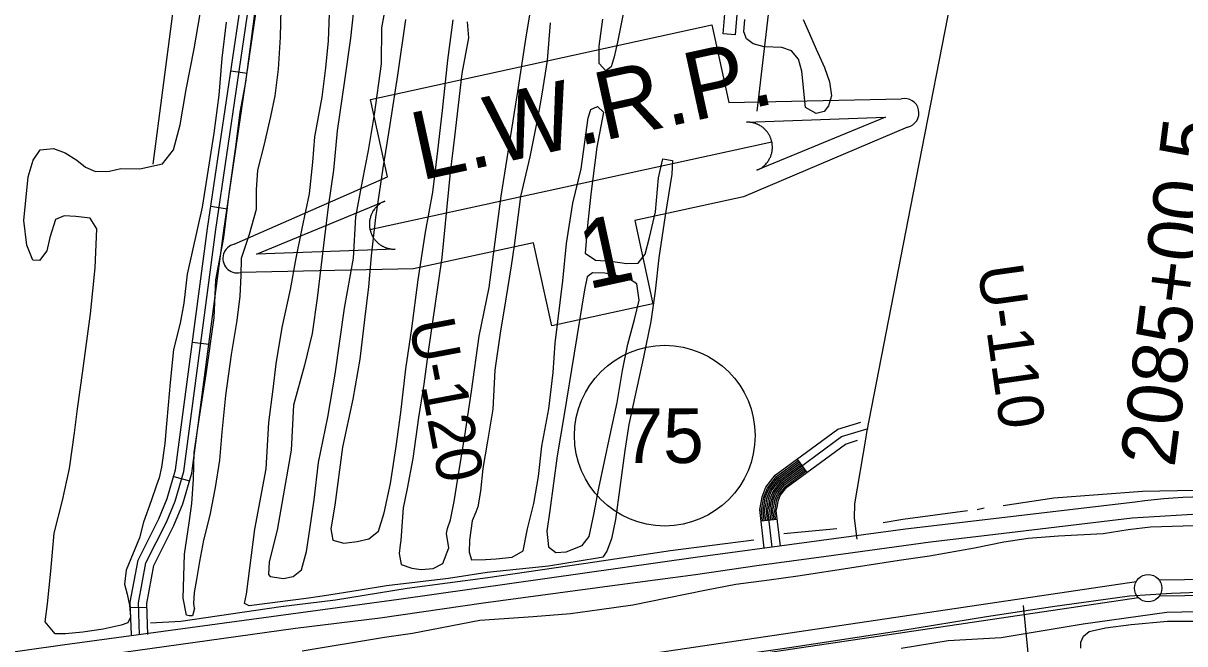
# Model space of a CAD drawing. Extents: x 3355677 to 3393573, y 612928 to 638357.
# Drawn here: x 3361105 to 3363227, y 625120 to 626253 of the extents above; entities that cross this region are included whole.
import ezdxf

# ---------------------------------------------------------------- set-up
doc = ezdxf.new("R2010")
doc.units = 0
for name, color, linetype in [('V-BLDG-OTLN', 7, 'Continuous'), ('V-FLOD-BASE', 7, 'Continuous'), ('V-LEVE-TOET', 7, 'Continuous'), ('V-RIVR-RANG', 7, 'Continuous'), ('V-RIVR-RANG-IDEN', 7, 'Continuous'), ('V-ROAD-CNTR', 7, 'Continuous'), ('V-ROAD-IDEN', 7, 'Continuous'), ('V-SITE-VEGE', 7, 'Continuous'), ('V-SURV-IDEN', 7, 'Continuous'), ('V-SURV-LINE', 7, 'Continuous'), ('V-TOPO-SHOR', 7, 'Continuous'), ('V-TOPO-WATR-IDEN', 7, 'Continuous')]:
    doc.layers.add(name, color=color, linetype=linetype)

msp = doc.modelspace()

# ---------------------------------------------------------------- linework, layer by layer
at = {"layer": 'V-BLDG-OTLN'}
msp.add_lwpolyline([(3362410, 626283.5), (3362406.1, 626232.2), (3362384.2, 626233.9), (3362388.1, 626285.1)], close=True, dxfattribs=at)
at = {"layer": 'V-FLOD-BASE'}
msp.add_lwpolyline([(3362000.8, 625039.3), (3362153.2, 625064.2), (3362360.8, 625092.7), (3362504.8, 625113.4), (3362708.5, 625144.1), (3362865.1, 625169.7), (3362985.4, 625188.2), (3363125.9, 625207.5), (3363202.8, 625212.6), (3363267.9, 625214.9), (3363381.2, 625216.6), (3363462.3, 625209.2), (3363630.2, 625192.8), (3363736.5, 625179.8), (3363859, 625167.6), (3363988.4, 625154.7), (3364110.1, 625139.6), (3364234, 625124.6), (3364270.4, 625117), (3364292.1, 625112.9)], dxfattribs=at)
at = {"layer": 'V-LEVE-TOET'}
for points in [[(3363323.1, 625337.9), (3363164.7, 625332.6), (3363123.5, 625328.3), (3363078.2, 625320.5), (3362996.6, 625316.7), (3362940.8, 625312.4), (3362896.8, 625305.3), (3362843.1, 625294.7), (3362760.8, 625279.8), (3362705.1, 625272), (3362587.9, 625253.5), (3362520.2, 625243.5), (3362467.9, 625236.4), (3362407.2, 625227.9), (3362353.5, 625217.9), (3362281.7, 625203.1), (3362218.9, 625190.4), (3362158.3, 625181.8), (3362105.3, 625174.7), (3362036.9, 625168.9), (3361939.2, 625162.4), (3361816.5, 625139), (3361765.6, 625131.2), (3361614.9, 625106.3)], [(3362709, 625111.7), (3362794.8, 625125.9), (3362891.7, 625131.7), (3363041.7, 625156.6), (3363194.4, 625177.9), (3363276.1, 625179.6), (3363339.6, 625178.3), (3363382.8, 625175.7), (3363437.3, 625174.4), (3363481.2, 625171.1), (3363538.5, 625165.6), (3363597.1, 625162.3), (3363659.2, 625154.1), (3363742.3, 625140.4), (3363811.4, 625130.1), (3363973.3, 625117.3)]]:
    msp.add_lwpolyline(points, dxfattribs=at)
at = {"layer": 'V-RIVR-RANG'}
msp.add_line((3362932, 625189.6), (3363059.6, 623895.8), dxfattribs=at)
at = {"layer": 'V-ROAD-CNTR'}
for p, q in [((3361484.7, 626166.2), (3361514.3, 626161.8)), ((3361448.2, 625918.9), (3361477.9, 625914.5)), ((3361414.7, 625670.9), (3361444.5, 625667)), ((3362519.1, 625457.1), (3362536.9, 625433)), ((3361380.3, 625425.7), (3361409.1, 625417.3)), ((3362453, 625344.3), (3362482.8, 625347.7)), ((3361301.4, 625186), (3361331.3, 625187))]:
    msp.add_line(p, q, dxfattribs=at)
for points in [[(3361333.1, 625137.1), (3361331.1, 625193.7), (3361343.9, 625263.1), (3361380.7, 625335.9), (3361396.9, 625375.4), (3361413.2, 625431.3), (3361472, 625874.4), (3361552.4, 626420.2), (3361626.5, 626944.1), (3361690.7, 627356), (3361764.8, 627926.7), (3361857.7, 628521.4), (3361932.7, 629031.3), (3361989.5, 629447.1), (3362043.4, 629781.8), (3362046.3, 629849.5), (3362026.4, 629885.3), (3362010.6, 629880.9)], [(3361303.1, 625136), (3361301, 625196), (3361315.2, 625272.8), (3361353.4, 625348.4), (3361368.5, 625385.3), (3361383.8, 625437.6), (3361442.3, 625878.6), (3361522.7, 626424.5), (3361596.8, 626948.5), (3361661, 627360.2), (3361735.1, 627930.9), (3361828, 628525.9), (3361903, 629035.5), (3361959.8, 629451.5), (3362013.5, 629784.8), (3362016, 629842.3), (3362011.6, 629850.1), (3362007.2, 629848.9), (3361989.5, 629843)], [(3361318.1, 625136.5), (3361316.1, 625194.9), (3361329.5, 625267.9), (3361367, 625342.1), (3361382.7, 625380.4), (3361398.5, 625434.5), (3361457.1, 625876.5), (3361537.6, 626422.4), (3361611.7, 626946.3), (3361675.9, 627358.1), (3361750, 627928.8), (3361842.9, 628523.6), (3361917.8, 629033.4), (3361974.6, 629449.3), (3362028.5, 629783.3), (3362031.1, 629845.9), (3362019, 629867.7), (3362002.8, 629863.2), (3361984.7, 629857.2)], [(3362866, 626637.9), (3362814.5, 626370.8), (3362726.3, 625918.7), (3362645.8, 625505.6), (3362643.6, 625493.9), (3362623.6, 625375.7), (3362623, 625349.1), (3362627.9, 625311)], [(3362458.7, 625294.6), (3362450.6, 625365), (3362453.5, 625377.9), (3362455.1, 625388.5), (3362462, 625405.8), (3362479.1, 625427.6), (3362593.4, 625511.8), (3362635.5, 625524.9)], [(3362473.6, 625296.3), (3362465.8, 625364.2), (3362468.3, 625375.2), (3362469.7, 625384.5), (3362475.1, 625398.2), (3362489.7, 625416.7), (3362600.2, 625498.3), (3362648.6, 625513.3)], [(3362488.5, 625298), (3362481, 625363.4), (3362483, 625372.4), (3362484.3, 625380.6), (3362488.3, 625390.7), (3362500.2, 625405.9), (3362607.1, 625484.7), (3362629.5, 625491.6)], [(3362456, 625344.6), (3362453.7, 625364.8), (3362456.5, 625377.4), (3362458, 625387.7), (3362464.6, 625404.3), (3362481.2, 625425.4), (3362520.9, 625454.7)], [(3362459, 625345), (3362456.7, 625364.7), (3362459.4, 625376.8), (3362460.9, 625386.9), (3362467.3, 625402.7), (3362483.3, 625423.2), (3362522.7, 625452.3)], [(3362461.9, 625345.3), (3362459.7, 625364.5), (3362462.4, 625376.3), (3362463.9, 625386.1), (3362469.9, 625401.2), (3362485.4, 625421.1), (3362524.5, 625449.9)], [(3362464.9, 625345.6), (3362462.8, 625364.4), (3362465.3, 625375.7), (3362466.8, 625385.3), (3362472.5, 625399.7), (3362487.5, 625418.9), (3362526.3, 625447.4)], [(3362467.9, 625346), (3362465.8, 625364.2), (3362468.3, 625375.2), (3362469.7, 625384.5), (3362475.1, 625398.2), (3362489.7, 625416.7), (3362528, 625445)], [(3362470.9, 625346.3), (3362468.9, 625364), (3362471.2, 625374.6), (3362472.6, 625383.7), (3362477.8, 625396.7), (3362491.8, 625414.6), (3362529.8, 625442.6)], [(3362473.9, 625346.7), (3362471.9, 625363.9), (3362474.2, 625374.1), (3362475.5, 625382.9), (3362480.4, 625395.2), (3362493.9, 625412.4), (3362531.6, 625440.2)], [(3362476.8, 625347), (3362474.9, 625363.7), (3362477.1, 625373.5), (3362478.4, 625382.2), (3362483, 625393.7), (3362496, 625410.2), (3362533.4, 625437.8)], [(3362479.8, 625347.3), (3362478, 625363.5), (3362480.1, 625373), (3362481.3, 625381.4), (3362485.6, 625392.2), (3362498.1, 625408), (3362535.2, 625435.4)], [(3363136.5, 625378.7), (3362716.8, 625329.1), (3362333.4, 625277.4), (3361791.5, 625201), (3361177, 625117.3), (3360797.8, 625064)]]:
    msp.add_lwpolyline(points, dxfattribs=at)
msp.add_arc((3363287.7, 624252.4), 1136.3, 83.5309, 97.6461, dxfattribs=at)
at = {"layer": 'V-ROAD-IDEN'}
msp.add_circle((3362277.3, 625500), 165, dxfattribs=at)
msp.add_circle((3362277.3, 625500), 165, dxfattribs=at)
at = {"layer": 'V-SITE-VEGE'}
for points in [[(3361916.3, 626255.8), (3361918.5, 626226.5), (3361906.8, 626161.5), (3361893.2, 626045.5), (3361885, 625980.5), (3361870.1, 625825.4), (3361857, 625737.4), (3361845.4, 625657.7), (3361837.2, 625594.1), (3361827.6, 625533.4), (3361817.3, 625458.6), (3361807, 625403.4), (3361799.4, 625368.4), (3361795.4, 625309), (3361794, 625300.7), (3361792, 625284.6), (3361795.5, 625265), (3361815.1, 625258.1), (3361832.5, 625255.4), (3361854.2, 625257.5), (3361871.6, 625266.7), (3361882.7, 625295.3), (3361878.5, 625321.2), (3361880.5, 625330.2), (3361886.1, 625346.3), (3361892.3, 625379.9), (3361899.1, 625421.8), (3361912.2, 625499.4), (3361924.5, 625580.4), (3361938.2, 625681.7), (3361956.8, 625770.5), (3361978.7, 625937.5), (3362008.9, 626128.3), (3362024.7, 626231.7), (3362042.5, 626337.2)], [(3361476.3, 626255.3), (3361468.1, 626189.6), (3361462.7, 626121.9), (3361453.8, 626052.7), (3361441.5, 625975.1), (3361432.5, 625917.1), (3361405, 625794.8), (3361398.8, 625741.7), (3361391.9, 625705.3), (3361380.2, 625657.1), (3361374.1, 625597), (3361370, 625555.8), (3361367.3, 625521.6), (3361363.9, 625485.9), (3361357.7, 625442.6), (3361353.6, 625423.1), (3361348.8, 625409.8), (3361339.1, 625381.1), (3361325.2, 625341.9), (3361317.6, 625313.3), (3361293.3, 625254.5), (3361290.6, 625228.7), (3361295.5, 625210.5), (3361299.8, 625190.3), (3361301.2, 625168.7), (3361296.4, 625158.2), (3361284.5, 625153.9), (3361251.7, 625146.9), (3361214, 625141.2), (3361182.6, 625138.3), (3361163.7, 625138.2), (3361145.5, 625159.8), (3361149.6, 625192.7), (3361155.7, 625252.8), (3361161.8, 625321.9), (3361177, 625381.3), (3361190.1, 625440.1), (3361199, 625505), (3361204.5, 625549.1), (3361214.1, 625618.2), (3361228.4, 625722.4), (3361236.6, 625806.2), (3361239.9, 625877.5), (3361227.9, 625897), (3361201.4, 625900.4), (3361180.4, 625901.7), (3361164.4, 625894.7), (3361154, 625861.8), (3361148.5, 625837.4), (3361135.3, 625819.9), (3361122.7, 625820.5), (3361112.1, 625847.8), (3361106.4, 625893.1), (3361114.6, 625972.8), (3361123.6, 626002.9), (3361136.1, 626021.7), (3361160.5, 626024.6), (3361182.2, 626016.3), (3361203.2, 626003.1), (3361219.3, 625990.5), (3361237.5, 625982.2), (3361263.3, 625983), (3361283.6, 625987.9), (3361318.5, 625987.3), (3361359.7, 625996.5), (3361379.9, 626021.7), (3361392.3, 626067.9), (3361403.3, 626132.2), (3361417.8, 626206.2), (3361432.2, 626291.5)], [(3361576.1, 626279.3), (3361574.9, 626227.6), (3361570.8, 626169), (3361564.7, 626120.7), (3361557.1, 626083), (3361544.7, 626029.9), (3361533.6, 625985.1), (3361530.9, 625948.8), (3361531, 625913.2), (3361517.9, 625867.1), (3361503.4, 625823.7), (3361502.7, 625792.3), (3361500.8, 625754.6), (3361495.3, 625710.5), (3361485, 625648.3), (3361474.7, 625573.6), (3361467.9, 625506.5), (3361463.9, 625455.5), (3361456.3, 625405.2), (3361446, 625354.9), (3361435, 625309.4), (3361427.4, 625270.3), (3361421.9, 625237.4), (3361417.8, 625213.7), (3361416.4, 625193.4), (3361417.8, 625185.1), (3361418.5, 625184.4), (3361414.4, 625171.1), (3361408.8, 625171.1), (3361403.9, 625172.4), (3361397.5, 625203.2), (3361400.1, 625283.5), (3361408.3, 625340.8), (3361413.1, 625376.4), (3361416.5, 625420.4), (3361417.7, 625469.3), (3361428, 625537.8), (3361439.7, 625612.6), (3361454.1, 625715.3), (3361457.4, 625784.5), (3361471.8, 625862), (3361481.4, 625941.7), (3361493.7, 626027.6), (3361501.9, 626090.5), (3361512.2, 626145.7), (3361530.7, 626289)], [(3361710.9, 626299.3), (3361703.4, 626225.9), (3361692.4, 626148.3), (3361678.7, 626056.8), (3361671.9, 625984.8), (3361662.3, 625917.8), (3361655.5, 625863.3), (3361642.6, 625750.8), (3361633, 625686.5), (3361619.2, 625628.5), (3361599.1, 625555.8), (3361595.1, 625473.3), (3361580, 625390.2), (3361569, 625327.3), (3361554.5, 625269.3), (3361553.2, 625246.2), (3361556.7, 625242.7), (3361581.1, 625239.3), (3361598.6, 625242.8), (3361613.9, 625254.8), (3361622.9, 625288.3), (3361629.1, 625328.8), (3361636.6, 625382.6), (3361644.8, 625451.1), (3361662, 625533.6), (3361675.1, 625612.5), (3361692.2, 625732.7), (3361708.7, 625824.3), (3361712.7, 625899.7), (3361725.1, 625964.7), (3361736.1, 626020.6), (3361747.1, 626086.3), (3361760.1, 626179.3), (3361760.6, 626244.9), (3361771.6, 626305)], [(3362277.8, 625902), (3362266.1, 625824.5), (3362260, 625763.7), (3362251.8, 625708.5), (3362238.7, 625643.5), (3362222.8, 625570.8), (3362211.8, 625520.5), (3362204.2, 625472.9), (3362195.3, 625405.2), (3362187.1, 625347.2), (3362180.2, 625311.5), (3362171.2, 625289.2), (3362164.3, 625278), (3362154.5, 625276.5), (3362065.1, 625261.6), (3361952.7, 625250.1), (3361882.2, 625239.4), (3361769.1, 625225.9), (3361717.4, 625217.3), (3361656, 625207.4), (3361622.4, 625202.4), (3361570.1, 625196), (3361518.4, 625189.5), (3361509.3, 625193.7), (3361513.5, 625210.5), (3361528.5, 625329.2), (3361549.1, 625439.7), (3361553.8, 625524.2), (3361562, 625585), (3361567.5, 625631.1), (3361578.5, 625697.5), (3361593.6, 625766.7), (3361603.9, 625824), (3361615, 625878.5), (3361628.1, 625941.4), (3361634.2, 625999.4), (3361638.2, 626045.5), (3361651.3, 626118.2), (3361658.1, 626172), (3361662.9, 626220.9), (3361664.8, 626270.5)], [(3362202.7, 626276.2), (3362191, 626218.9), (3362184.7, 626191.6), (3362179.2, 626173.5), (3362169.4, 626166.4), (3362157.5, 626179.7), (3362157.4, 626211.1), (3362164.3, 626260.7)], [(3361803.9, 626259.7), (3361788.8, 626158.4), (3361775.1, 626068.2), (3361762, 625988.6), (3361749, 625898.4), (3361740.8, 625828.6), (3361736.1, 625772), (3361729.3, 625716.8), (3361720.4, 625639.9), (3361707.3, 625566.5), (3361688.7, 625479.2), (3361674.4, 625373), (3361667.5, 625329.6), (3361671, 625309.4), (3361691.3, 625303.9), (3361715.1, 625306.7), (3361736.7, 625311.7), (3361754.1, 625325.7), (3361764.5, 625359.2), (3361776.2, 625412.4), (3361786.5, 625480.2), (3361795.4, 625542.3), (3361804.3, 625622), (3361815.2, 625695.4), (3361826.9, 625784.8), (3361839.9, 625871.5), (3361853.7, 625944.8), (3361862.5, 626020.3), (3361871.4, 626093.7), (3361880.9, 626185.9), (3361890.5, 626259.3)], [(3362067.9, 626254.2), (3362062.5, 626185), (3362052.9, 626123.5), (3362045.4, 626082.3), (3362030.9, 626008.9), (3362013.6, 625936.9), (3362002, 625847.5), (3361996.5, 625810.4), (3361986.9, 625749.6), (3361976.6, 625687.4), (3361967, 625619.7), (3361963, 625548.4), (3361953.4, 625489.7), (3361945.2, 625440.1), (3361940.4, 625398.9), (3361935.6, 625370.2), (3361932.1, 625360.4), (3361925.2, 625344.3), (3361920.4, 625309.4), (3361919.8, 625287), (3361924, 625273.1), (3361949.8, 625273.9), (3361969.4, 625275.3), (3361998.7, 625278.2), (3362018.3, 625289.4), (3362026.5, 625330), (3362038.3, 625376.1), (3362046.5, 625425.7), (3362052.6, 625480.9), (3362065.7, 625548.7), (3362073.2, 625615.1), (3362077.3, 625668.9), (3362090.9, 625782.8), (3362097.7, 625851.2), (3362109.4, 625924.6), (3362124.6, 625987.5), (3362137.6, 626080.4), (3362142.4, 626095.8), (3362154.3, 626101.4), (3362165.5, 626091), (3362153.1, 626026.7), (3362142.1, 625940.8), (3362136, 625883.5), (3362132, 625833.2), (3362150.9, 625820.6), (3362178.8, 625818.6), (3362207.5, 625814.5), (3362228.4, 625815.3), (3362241.6, 625831.4), (3362249.2, 625862.1), (3362260.3, 625909), (3362265.7, 625971.1), (3362274, 626005.4), (3362291.4, 626002.6), (3362290.1, 625977.5), (3362277.8, 625902)], [(3362530.3, 626259.7), (3362541.6, 626233.9), (3362553.5, 626205.9), (3362569, 626172.5), (3362578.1, 626145.9), (3362581.7, 626120.8), (3362576.2, 626102.6), (3362568.5, 626092.1), (3362553.8, 626088.6), (3362534.3, 626099), (3362527.8, 626165.4), (3362521.4, 626187.7), (3362508.8, 626203), (3362491.3, 626208.6), (3362458.5, 626209.9), (3362438.9, 626215.4), (3362426.3, 626224.4), (3362421.4, 626237.7), (3362423.4, 626260.1)], [(3363037.1, 625112.1), (3363037, 625122.6), (3363041.9, 625133.8), (3363052.4, 625142.3), (3363082.4, 625149.3), (3363129.3, 625155.1), (3363195.7, 625161.5), (3363291.5, 625161.1), (3363356.6, 625155.7), (3363411.8, 625146.1), (3363455.2, 625139.2), (3363494.4, 625134.4), (3363532.2, 625135.9), (3363570.6, 625141.6), (3363618.9, 625142.4), (3363668.6, 625136.3), (3363718.9, 625126.6), (3363753.2, 625118.3)]]:
    msp.add_lwpolyline(points, dxfattribs=at)
msp.add_lwpolyline([(3362130.6, 625766.1), (3362092.9, 625535), (3362080.6, 625463.1), (3362067.6, 625363.3), (3362062.1, 625325.6), (3362065, 625297), (3362078.3, 625286.6), (3362097.1, 625288), (3362126.4, 625299.3), (3362138.9, 625316), (3362147.8, 625355.8), (3362156.8, 625404), (3362177.4, 625501.7), (3362190.5, 625560.4), (3362200.1, 625619), (3362209.8, 625667.2), (3362222.2, 625711.9), (3362230.5, 625747.5), (3362226.2, 625777.5), (3362210.8, 625787.2), (3362192, 625792.1), (3362167.5, 625796.9), (3362145.2, 625797.5), (3362135.5, 625789.8)], close=True, dxfattribs=at)
at = {"layer": 'V-SURV-LINE'}
for points in [[(3360482.2, 624839.8), (3363138.1, 625233.5)], [(3363179.9, 625236.8), (3363367.5, 625239.4)], [(3363142.5, 625203.8), (3360486.5, 624810.1)], [(3363368, 625209.5), (3363180.3, 625206.8)]]:
    msp.add_lwpolyline(points, dxfattribs=at)
msp.add_circle((3363160.1, 625221.6), 25, dxfattribs=at)
at = {"layer": 'V-TOPO-SHOR'}
for p, q in [((3362445.9, 626092.5), (3362548.9, 626977.1)), ((3362860.8, 625367.4), (3362847.6, 625364.6)), ((3362591.7, 625329.6), (3362494.5, 625320.9))]:
    msp.add_line(p, q, dxfattribs=at)
for points in [[(3361342.5, 625995.6), (3361448.5, 626807.4), (3361581.8, 627791.9), (3361657.5, 628370.5)], [(3363245.4, 625400), (3363149.6, 625398.3), (3362988.1, 625386), (3362895.1, 625371.7)], [(3361127.5, 625081.9), (3361602.9, 625148.3), (3361757.4, 625167.6), (3361946.1, 625194.7), (3362185.9, 625226.9), (3362333.5, 625246.2), (3362445.3, 625263.2), (3362571.9, 625279.7), (3362762.7, 625306.1), (3362881.6, 625320.4), (3363131.2, 625349.8), (3363271.7, 625358.6), (3363345.2, 625358.8), (3363420, 625356.2), (3363538.9, 625350.3), (3363628.5, 625340), (3363785.9, 625324.4), (3363904.8, 625307.2), (3364086.7, 625288.9)], [(3362830.1, 625362.5), (3362711.9, 625346.7), (3362676.3, 625341)], [(3362440, 625308.9), (3362287.6, 625289.6), (3362149.8, 625268.9), (3361954.1, 625240.4), (3361806.6, 625221.1), (3361675.8, 625199.7), (3361575.9, 625187.6), (3361393.4, 625160.5), (3361338.2, 625157.5)]]:
    msp.add_lwpolyline(points, dxfattribs=at)
at = {"layer": 'V-TOPO-WATR-IDEN'}
msp.add_line((3361738.8, 625876.5), (3362472.8, 626036.5), dxfattribs=at)
for points in [[(3361490.9, 625849.6), (3361770.5, 625972.7), (3361739.6, 626114.1), (3362363.5, 626250.1), (3362394.3, 626108.7), (3362709.4, 626115.3)], [(3362720.7, 626063.4), (3362421.1, 625936), (3362222.4, 625892.7), (3362255.5, 625740.9), (3362070.7, 625700.7), (3362037.6, 625852.4), (3361818, 625804.5), (3361502.2, 625797.8)]]:
    msp.add_lwpolyline(points, dxfattribs=at)
for points in [[(3362426.6, 626072.5), (3362680.3, 626081.8), (3362445.7, 625984.6), (3362449.9, 625986.5), (3362453.6, 625988.8), (3362455.1, 625989.8), (3362456.3, 625990.8), (3362457.8, 625992), (3362459.2, 625993.2), (3362460.3, 625994.3), (3362461.8, 625995.9), (3362463.3, 625997.6), (3362464.2, 625998.6), (3362465.2, 626000), (3362466.4, 626001.8), (3362467.3, 626003.3), (3362468.2, 626004.9), (3362468.8, 626006), (3362469.4, 626007.2), (3362470.1, 626008.6), (3362470.7, 626010), (3362471.2, 626011.5), (3362471.6, 626012.6), (3362472.1, 626014.4), (3362472.6, 626016.1), (3362472.9, 626017.4), (3362473.2, 626019.1), (3362473.4, 626020.5), (3362473.6, 626021.7), (3362473.7, 626022.7), (3362473.8, 626024.2), (3362473.8, 626025.8), (3362473.8, 626027.2), (3362473.8, 626028.7), (3362473.7, 626030.1), (3362473.6, 626031.6), (3362473.4, 626032.8), (3362473.2, 626034.6), (3362472.8, 626036.5), (3362472.6, 626037.2), (3362472.4, 626038.1), (3362472.1, 626039.1), (3362471.8, 626040.1), (3362471.5, 626041.1), (3362471.2, 626042.1), (3362470.8, 626043.2), (3362470.5, 626044), (3362470, 626045.1), (3362469.6, 626046.1), (3362469.2, 626046.8), (3362468.3, 626048.6), (3362467.8, 626049.6), (3362467.4, 626050.2), (3362466.7, 626051.3), (3362466.2, 626052.2), (3362465.5, 626053.1), (3362464.7, 626054.2), (3362463.9, 626055.2), (3362463.3, 626056), (3362462.8, 626056.6), (3362462, 626057.5), (3362461.3, 626058.2), (3362460.5, 626059.1), (3362459.6, 626059.9), (3362458.7, 626060.8), (3362457.6, 626061.8), (3362456.7, 626062.5), (3362455.7, 626063.2), (3362454.8, 626063.9), (3362454, 626064.5), (3362453.1, 626065.1), (3362451.8, 626065.9), (3362451.7, 626066), (3362450.9, 626066.4), (3362450.3, 626066.8), (3362449.4, 626067.3), (3362448.3, 626067.9), (3362447.3, 626068.3), (3362446.5, 626068.7), (3362445.4, 626069.1), (3362444.4, 626069.6), (3362443.6, 626069.8), (3362442.6, 626070.2), (3362441.2, 626070.6), (3362440.4, 626070.9), (3362439.7, 626071), (3362439.1, 626071.2), (3362438.4, 626071.4), (3362437.4, 626071.6), (3362436.5, 626071.8), (3362435.5, 626071.9), (3362434.6, 626072.1), (3362433.3, 626072.2), (3362432.6, 626072.3), (3362431.4, 626072.4), (3362430, 626072.5), (3362429, 626072.5), (3362428.2, 626072.5), (3362427.5, 626072.5), (3362426.9, 626072.5)], [(3361785, 625840.6), (3361531.3, 625831.3), (3361765.9, 625928.5), (3361761.8, 625926.5), (3361758, 625924.3), (3361756.5, 625923.2), (3361755.3, 625922.3), (3361753.8, 625921.1), (3361752.5, 625919.9), (3361751.3, 625918.8), (3361749.8, 625917.2), (3361748.3, 625915.5), (3361747.5, 625914.4), (3361746.5, 625913.1), (3361745.2, 625911.3), (3361744.3, 625909.8), (3361743.4, 625908.2), (3361742.8, 625907.1), (3361742.2, 625905.9), (3361741.5, 625904.4), (3361740.9, 625903), (3361740.4, 625901.6), (3361740, 625900.5), (3361739.5, 625898.7), (3361739, 625897), (3361738.7, 625895.6), (3361738.4, 625894), (3361738.2, 625892.6), (3361738.1, 625891.4), (3361738, 625890.4), (3361737.8, 625888.9), (3361737.8, 625887.3), (3361737.8, 625885.9), (3361737.8, 625884.4), (3361737.9, 625883), (3361738, 625881.5), (3361738.2, 625880.2), (3361738.4, 625878.5), (3361738.8, 625876.5), (3361739, 625875.9), (3361739.2, 625875), (3361739.5, 625874), (3361739.8, 625872.9), (3361740.1, 625872), (3361740.4, 625871), (3361740.8, 625869.9), (3361741.1, 625869.1), (3361741.6, 625868), (3361742.1, 625867), (3361742.4, 625866.3), (3361743.3, 625864.5), (3361743.8, 625863.5), (3361744.2, 625862.9), (3361744.9, 625861.8), (3361745.5, 625860.9), (3361746.1, 625860), (3361746.9, 625858.9), (3361747.7, 625857.9), (3361748.3, 625857.1), (3361748.8, 625856.5), (3361749.6, 625855.6), (3361750.3, 625854.9), (3361751.1, 625854), (3361752, 625853.2), (3361752.9, 625852.3), (3361754, 625851.3), (3361754.9, 625850.6), (3361755.9, 625849.9), (3361756.8, 625849.1), (3361757.6, 625848.6), (3361758.5, 625848), (3361759.8, 625847.2), (3361759.9, 625847.1), (3361760.7, 625846.6), (3361761.3, 625846.3), (3361762.2, 625845.8), (3361763.3, 625845.2), (3361764.3, 625844.8), (3361765.1, 625844.4), (3361766.2, 625844), (3361767.3, 625843.5), (3361768, 625843.3), (3361769, 625842.9), (3361770.4, 625842.5), (3361771.2, 625842.2), (3361771.9, 625842), (3361772.5, 625841.9), (3361773.2, 625841.7), (3361774.2, 625841.5), (3361775.1, 625841.3), (3361776.1, 625841.1), (3361777.1, 625841), (3361778.3, 625840.8), (3361779, 625840.8), (3361780.2, 625840.7), (3361781.6, 625840.6), (3361782.6, 625840.6), (3361783.4, 625840.5), (3361784.2, 625840.5), (3361784.7, 625840.6)]]:
    msp.add_lwpolyline(points, close=True, dxfattribs=at)
for centre, start, end in [((3362715.1, 626089.3), 282.2966, 102.2966), ((3361496.5, 625823.7), 102.2966, 282.2966)]:
    msp.add_arc(centre, 26.5, start, end, dxfattribs=at)

# ---------------------------------------------------------------- texts
at = {"layer": 'V-RIVR-RANG-IDEN'}
for s, rotation, p in [('U-110', 278.0635, (3362848.5, 625807.5)), ('U-120', 280.7223, (3361809.7, 625706.7))]:
    msp.add_text(s, height=83, rotation=rotation, dxfattribs=at).set_placement(p)
at = {"layer": 'V-ROAD-IDEN'}
msp.add_text('75', height=100, rotation=0.15, dxfattribs=at).set_placement((3362199.9, 625449.8))
at = {"layer": 'V-SURV-IDEN'}
msp.add_text('2085+00.5', height=100, rotation=82.8037, dxfattribs=at).set_placement((3363208.2, 625440.8))
at = {"layer": 'V-TOPO-WATR-IDEN'}
for s, rotation, p in [('L.W.R.P.', 12.2965, (3361831.1, 625965.7)), ('1', 12.2966, (3362136.4, 625766.7))]:
    msp.add_text(s, height=124.5, rotation=rotation, dxfattribs=at).set_placement(p)

doc.saveas('drawing.dxf')
